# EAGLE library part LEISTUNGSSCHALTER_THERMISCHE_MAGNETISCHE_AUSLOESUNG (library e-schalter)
Leistungsschalter mit thermischer/magnetischer Auslösung
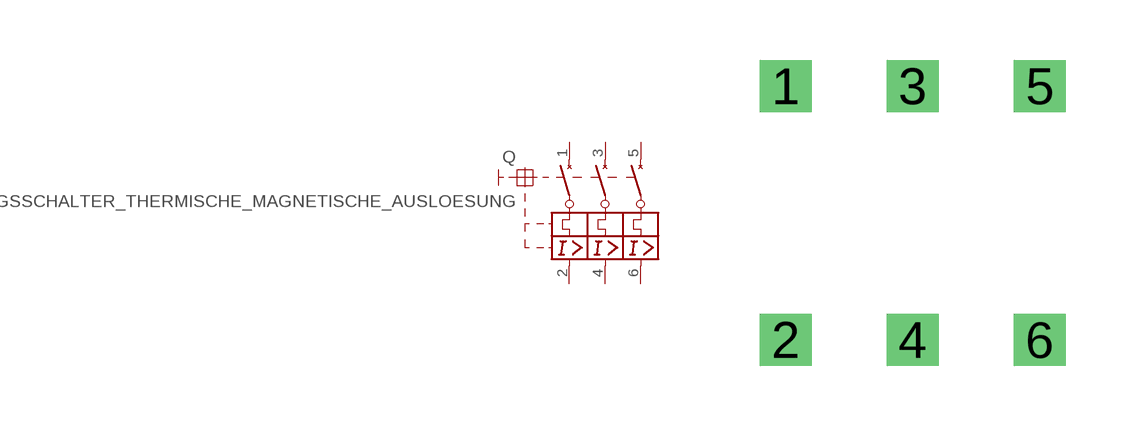
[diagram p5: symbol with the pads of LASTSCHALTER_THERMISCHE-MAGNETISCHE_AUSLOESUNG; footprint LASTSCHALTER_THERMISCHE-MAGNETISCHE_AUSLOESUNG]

Designator prefix Q

## LEISTUNGSSCHALTER_THERMISCHE_MAGNETISCHE_AUSLOESUNG  [LASTSCHALTER_THERMISCHE-MAGNETISCHE_AUSLOESUNG]
1  1  pas
2  2  pas
3  3  pas
4  4  pas
5  5  pas
6  6  pas

## Footprint LASTSCHALTER_THERMISCHE-MAGNETISCHE_AUSLOESUNG (pad centres in mm)
Dummy
drill 0.8 square: 1 -3.175,3.175; 2 -3.175,-3.175; 3 0,3.175; 4 0,-3.175; 5 3.175,3.175; 6 3.175,-3.175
